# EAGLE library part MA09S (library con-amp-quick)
AMP QUICK CONNECTOR
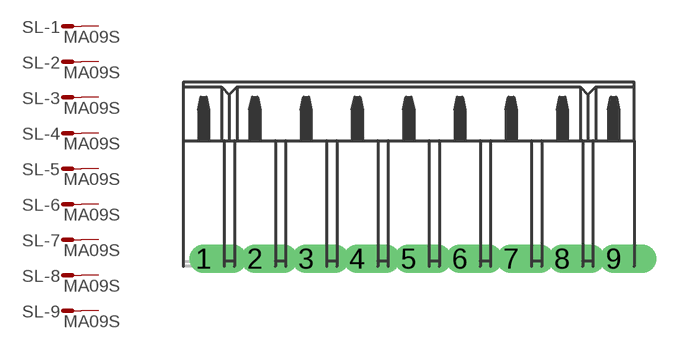
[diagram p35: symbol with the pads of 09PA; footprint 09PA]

Designator prefix SL; gates -1=M -2=M -3=M -4=M -5=M -6=M -7=M -8=M -9=M

## MA09S  [09PA]
1  -1:S  pas
2  -2:S  pas
3  -3:S  pas
4  -4:S  pas
5  -5:S  pas
6  -6:S  pas
7  -7:S  pas
8  -8:S  pas
9  -9:S  pas

## Footprint 09PA (pad centres in mm)
AMP QUICK CONNECTOR
drill 0.914 offset: 1 -10.16,0; 2 -7.62,0; 3 -5.08,0; 4 -2.54,0; 5 0,0; 6 2.54,0; 7 5.08,0; 8 7.62,0; 9 10.16,0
